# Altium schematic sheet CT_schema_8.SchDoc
size 274 x 160 mm
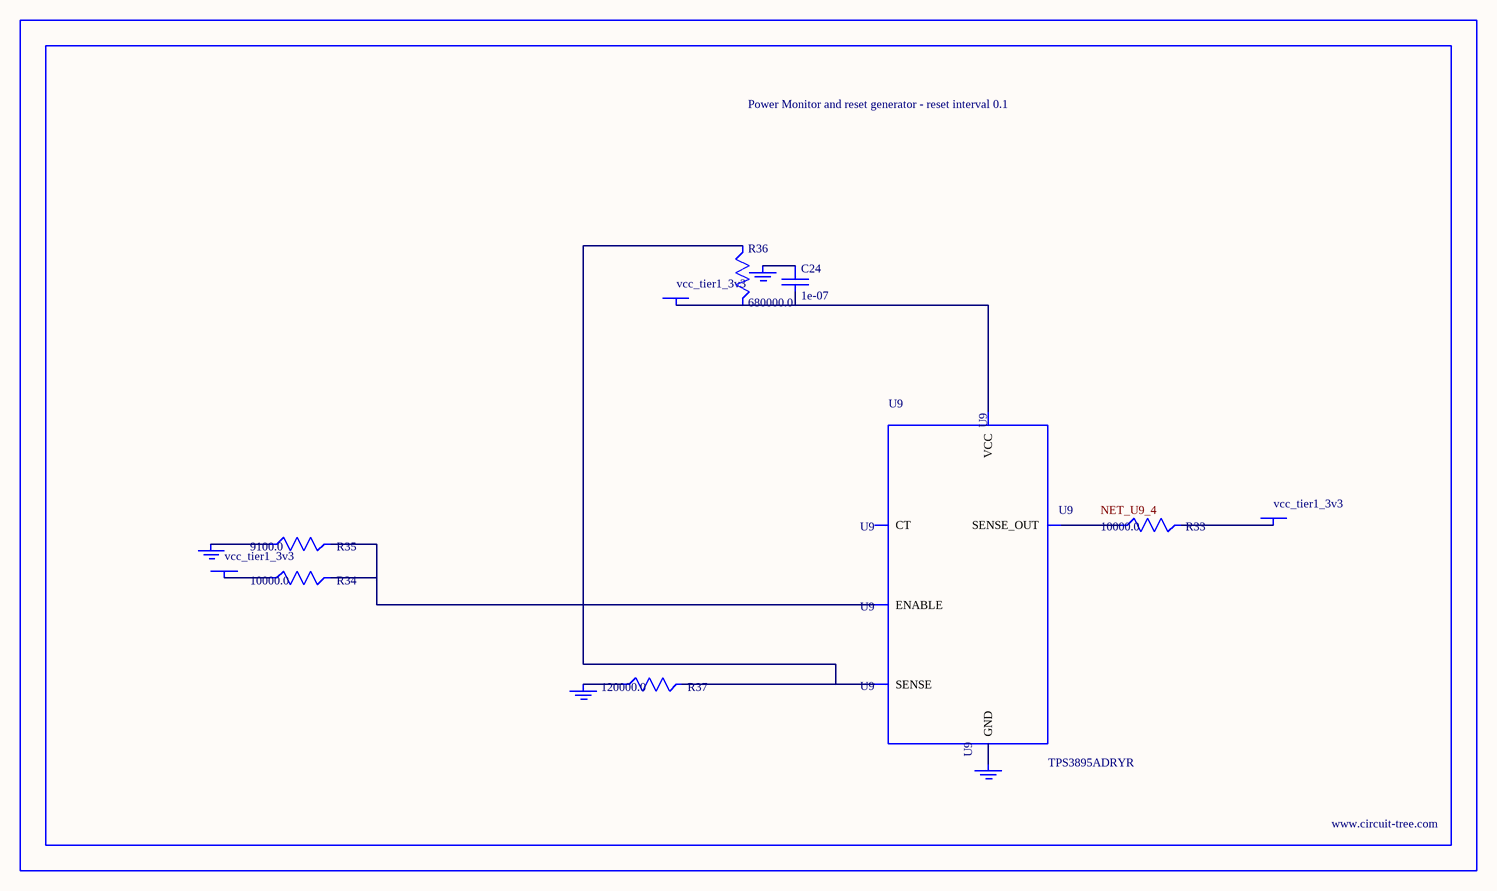
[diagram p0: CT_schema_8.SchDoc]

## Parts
BORDER7  (no value)
C24  1e-07  [C0402]
GND_INSTANCE_7_0  (no value)
GND_INSTANCE_7_1  (no value)
GND_INSTANCE_7_2  (no value)
GND_INSTANCE_7_3  (no value)
POWER_INSTANCE_7_0  vcc_tier1_3v3
POWER_INSTANCE_7_1  vcc_tier1_3v3
POWER_INSTANCE_7_2  vcc_tier1_3v3
R33  10000.0  [R0603]
R34  10000.0  [R0603]
R35  9100.0  [R0603]
R36  680000.0  [R0603]
R37  120000.0  [R0603]
U9  TPS3895ADRYR  [SON-6]

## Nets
NetC24_1: C24.1 GND_INSTANCE_7_2.0(GND)
NetC24_2: C24.2 POWER_INSTANCE_7_2.0(PWR) R36.2 U9.6(VCC)
NetGND_INSTANCE_7_0_0: GND_INSTANCE_7_0.0(GND) R35.1
NetGND_INSTANCE_7_1_0: GND_INSTANCE_7_1.0(GND) R37.1
NetGND_INSTANCE_7_3_0: GND_INSTANCE_7_3.0(GND) U9.2(GND)
NetPOWER_INSTANCE_7_0_0: POWER_INSTANCE_7_0.0(PWR) R34.1
NetPOWER_INSTANCE_7_1_0: POWER_INSTANCE_7_1.0(PWR) R33.2
NetR33_1: R33.1 U9.4(SENSE_OUT)
NetR34_2: R34.2 R35.2 U9.1(ENABLE)
NetR36_1: R36.1 R37.2 U9.3(SENSE)

Not connected (* = marked no-connect by the designer): U9 5(CT)

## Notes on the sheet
- Labels drawn without touching a wire or pin: NET_U9_4

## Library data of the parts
BORDER7 = BORDER_PAGE7
C24 = C0402C104K3RACTU
GND_INSTANCE_7_0-GND_INSTANCE_7_3 = GND
POWER_INSTANCE_7_0-POWER_INSTANCE_7_2 = PWR
R33 R34 = RC0603JR-0710KL
R35 = RC0603JR-079K1L
R36 = RC0603JR-07680KL
R37 = RC0603JR-07120KL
